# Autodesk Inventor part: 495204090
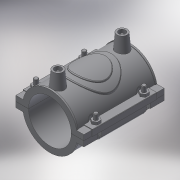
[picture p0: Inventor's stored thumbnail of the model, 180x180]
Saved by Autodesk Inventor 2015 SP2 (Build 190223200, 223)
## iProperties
Created: 2017-07
Part Number: 495204090
Material: Generic
Description: PLASSON REPAIR SADDLE 90
Document SubType Name: Modeling
Designer: KIM
Density: 1 g/cm^3
Appearance: Default
Author: KIM
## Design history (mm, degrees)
derived "495204.ipt"
feature "Solid1::495204.ipt"
tag "TaggingFeature1"
body "Solid1"
other parameters: "d1" = 109.8, "d2" = 126, "d3" = 22.5, "d4" = 118, "d5" = 0, "d6" = 0.1, "d8" = 0, "d19" = 6, "d20" = 6, "d21" = 70.8, "d23" = 0, "d24" = 35.4, "d26" = 0, "d27" = 3, "d28" = 3, "d29" = 3, "d31" = 6, "d32" = 0, "d33" = 0, "d34" = 0.6, "d40" = 57.096, "d41" = 64.9, "d43" = 0, "d45" = 0, "d47" = 59.292, "d48" = 47.2, "d50" = 0, "d70" = 15, "d72" = 0, "d73" = 6, "d75" = 5, "d76" = 0, "d77" = 4.5, "d78" = 74, "d79" = 15, "d80" = 47.2, "d82" = 5 deg, "d84" = 4, "d85" = 14, "d86" = 0, "d87" = 3, "d88" = 0, "d89" = 1, "d90" = 1, "d91" = 94.4, "d92" = 0, "d93" = 0.5, "d94" = 47.36842, "d96" = 111.996, "d97" = 2.36, "d98" = 0, "d99" = 47.2, "d100" = 0, "d102" = 2.36, "B_" = 126, "H_" = 29, "L_" = 118, "d_t" = 6
